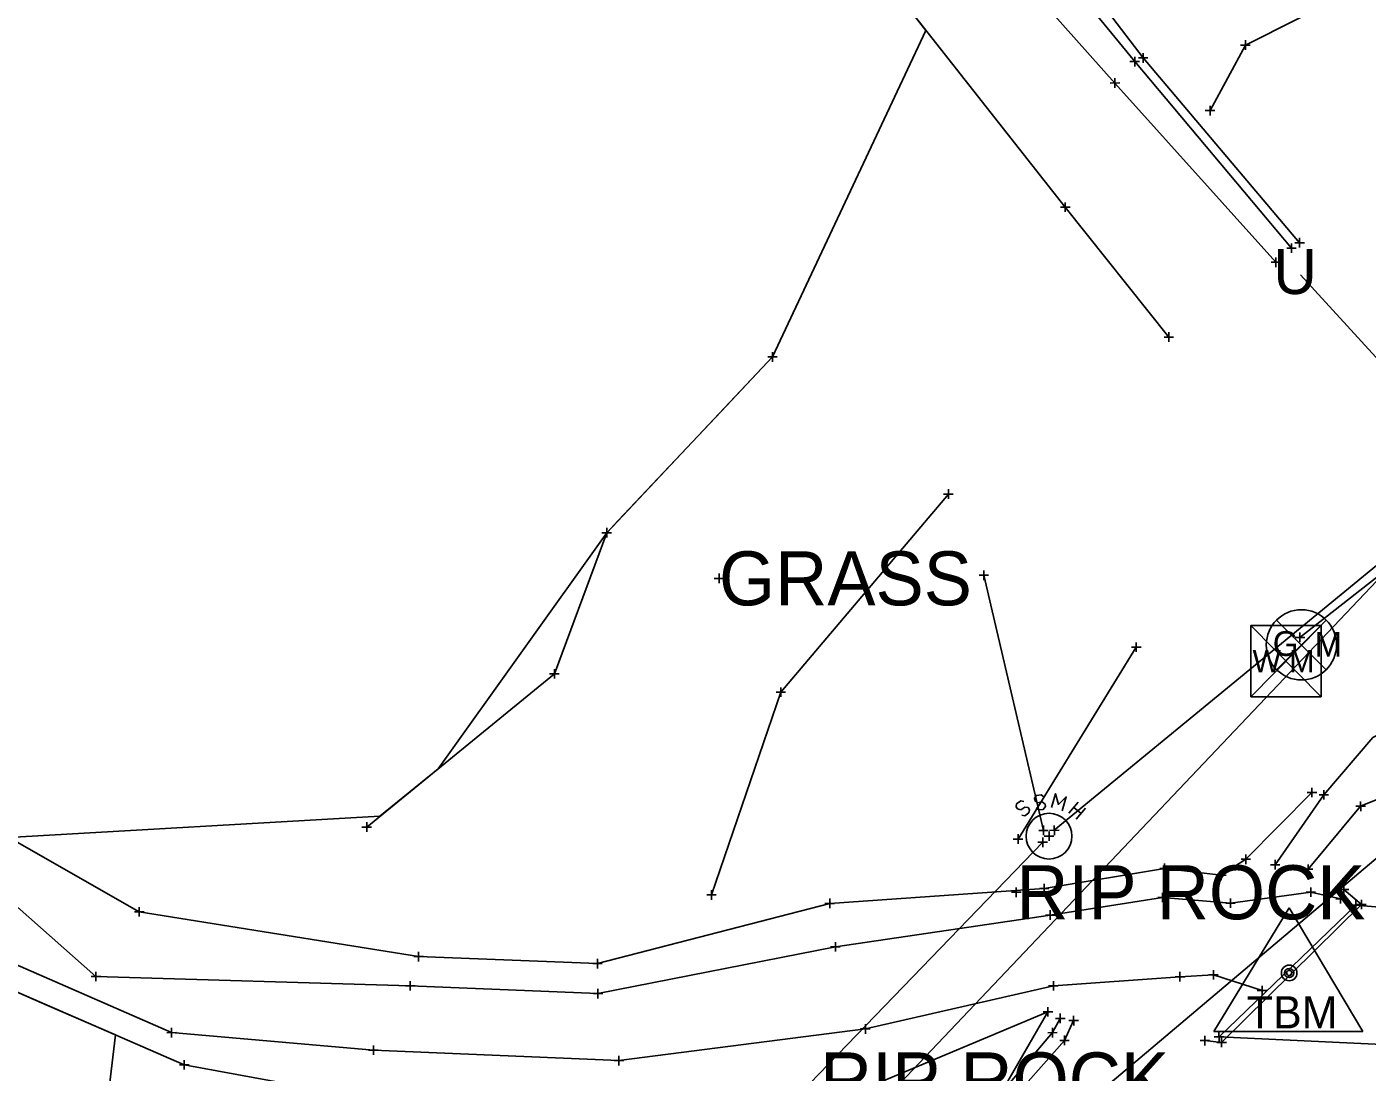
# Model space of a CAD drawing. Extents: x -1 to 1157254, y -1 to 2021979.
# Drawn here: x 1149359.7 to 1149538.4, y 2019032.4 to 2019171.7 of the extents above; entities that cross this region are included whole.
import ezdxf

# ---------------------------------------------------------------- set-up
doc = ezdxf.new("R2010")
doc.units = 0
for name, color, linetype in [('S_AREA_CALC', 7, 'Continuous'), ('S_BUILDING_ANNOT', 7, 'Continuous'), ('S_CAL_CORNER_ANNOT', 7, 'Continuous'), ('S_CONTOUR_ANNOT', 7, 'Continuous'), ('S_CONTOUR_MAJOR', 7, 'Continuous'), ('S_CONTOUR_MINOR', 7, 'Continuous'), ('S_CTL_TABLE', 7, 'Continuous'), ('S_DRIVEWAY_ANNOT', 7, 'Continuous'), ('S_DROP_INLET', 7, 'Continuous'), ('S_EDGE_BITUMINOUS_ANNOT', 7, 'Continuous'), ('S_ELECTRIC_UTILITIES_ANNOT', 7, 'Continuous'), ('S_ENV_CONSTRAINT', 7, 'Continuous'), ('S_EXIST_ROW', 7, 'Continuous'), ('S_GAS_PUMP_ISLAND_ANNOT', 7, 'Continuous'), ('S_GATE', 7, 'Continuous')]:
    doc.layers.add(name, color=color, linetype=linetype)

msp = doc.modelspace()

# ---------------------------------------------------------------- linework, layer by layer
at = {"layer": 'S_AREA_CALC'}
for p, q in [((1149527.99, 2019054.31), (1149517.96, 2019037.8)), ((1149527.99, 2019054.31), (1149537.81, 2019037.8)), ((1149517.96, 2019037.8), (1149537.81, 2019037.8))]:
    msp.add_line(p, q, dxfattribs=at)
for radius in [1.04, 0.609, 0.344]:
    msp.add_circle((1149527.99, 2019045.61), radius, dxfattribs=at)
at = {"layer": 'S_BUILDING_ANNOT'}
for p, q in [((1149507.41, 2019166.42), (1149507.41, 2019167.7)), ((1149508.54, 2019166.9), (1149508.54, 2019168.18)), ((1149506.77, 2019167.06), (1149508.05, 2019167.06)), ((1149507.41, 2019167.06), (1149507.41, 2019167.06)), ((1149507.9, 2019167.54), (1149509.17, 2019167.54)), ((1149508.54, 2019167.54), (1149508.54, 2019167.54)), ((1149504.13, 2019164.19), (1149505.41, 2019164.2)), ((1149504.77, 2019163.56), (1149504.77, 2019164.83)), ((1149504.77, 2019164.19), (1149504.77, 2019164.19)), ((1149498.15, 2019147.01), (1149498.15, 2019148.28)), ((1149497.51, 2019147.65), (1149498.78, 2019147.65)), ((1149498.15, 2019147.65), (1149498.15, 2019147.65)), ((1149528.31, 2019141.56), (1149528.31, 2019142.83)), ((1149528.74, 2019142.92), (1149530.01, 2019142.92)), ((1149529.37, 2019142.29), (1149529.37, 2019143.56)), ((1149529.37, 2019142.92), (1149529.37, 2019142.92)), ((1149526.22, 2019139.68), (1149526.22, 2019140.95)), ((1149527.67, 2019142.2), (1149528.94, 2019142.2)), ((1149528.31, 2019142.2), (1149528.31, 2019142.2)), ((1149525.59, 2019140.31), (1149526.86, 2019140.32)), ((1149526.22, 2019140.32), (1149526.22, 2019140.32)), ((1149511.31, 2019130.35), (1149512.59, 2019130.35)), ((1149511.95, 2019129.71), (1149511.95, 2019130.98)), ((1149511.95, 2019130.35), (1149511.95, 2019130.35)), ((1149451.36, 2019098.19), (1149452.63, 2019098.19)), ((1149451.99, 2019097.56), (1149451.99, 2019098.83)), ((1149451.99, 2019098.19), (1149451.99, 2019098.19)), ((1149486.66, 2019098.6), (1149487.93, 2019098.6)), ((1149487.29, 2019097.97), (1149487.29, 2019099.24)), ((1149487.29, 2019098.6), (1149487.29, 2019098.6)), ((1149529.43, 2019089.69), (1149529.42, 2019090.97)), ((1149528.79, 2019090.33), (1149530.06, 2019090.33)), ((1149529.43, 2019090.33), (1149529.43, 2019090.33)), ((1149531.98, 2019069.35), (1149533.25, 2019069.35)), ((1149532.62, 2019068.71), (1149532.62, 2019069.98)), ((1149532.62, 2019069.35), (1149532.62, 2019069.35)), ((1149536.88, 2019067.83), (1149538.15, 2019067.83)), ((1149537.52, 2019067.19), (1149537.51, 2019068.47)), ((1149537.51, 2019067.83), (1149537.51, 2019067.83)), ((1149494.6, 2019064.61), (1149495.87, 2019064.61)), ((1149494.6, 2019064.61), (1149495.87, 2019064.61)), ((1149495.23, 2019063.97), (1149495.23, 2019065.24)), ((1149495.23, 2019063.97), (1149495.23, 2019065.24)), ((1149495.23, 2019064.61), (1149495.23, 2019064.61)), ((1149495.23, 2019064.61), (1149495.23, 2019064.61)), ((1149495.98, 2019063.2), (1149495.98, 2019064.47)), ((1149496.05, 2019064.61), (1149497.32, 2019064.62)), ((1149496.05, 2019064.61), (1149497.32, 2019064.62)), ((1149496.69, 2019063.98), (1149496.68, 2019065.25)), ((1149496.69, 2019063.98), (1149496.68, 2019065.25)), ((1149496.68, 2019064.62), (1149496.68, 2019064.62)), ((1149496.68, 2019064.62), (1149496.68, 2019064.62)), ((1149494.5, 2019063.02), (1149495.78, 2019063.02)), ((1149494.5, 2019063.02), (1149495.78, 2019063.02)), ((1149495.14, 2019062.38), (1149495.14, 2019063.66)), ((1149495.14, 2019062.38), (1149495.14, 2019063.66)), ((1149495.14, 2019063.02), (1149495.14, 2019063.02)), ((1149495.14, 2019063.02), (1149495.14, 2019063.02)), ((1149495.34, 2019063.84), (1149496.62, 2019063.84)), ((1149495.98, 2019063.84), (1149495.98, 2019063.84)), ((1149526.12, 2019059.4), (1149526.12, 2019060.67)), ((1149525.49, 2019060.03), (1149526.76, 2019060.03)), ((1149526.12, 2019060.03), (1149526.12, 2019060.03)), ((1149529.88, 2019059.45), (1149531.15, 2019059.45)), ((1149530.52, 2019058.81), (1149530.52, 2019060.08)), ((1149530.52, 2019059.45), (1149530.52, 2019059.45)), ((1149491.61, 2019055.73), (1149491.61, 2019057)), ((1149530.88, 2019055.75), (1149530.87, 2019057.02)), ((1149535.28, 2019056.1), (1149535.28, 2019057.37)), ((1149490.97, 2019056.36), (1149492.25, 2019056.36)), ((1149491.61, 2019056.36), (1149491.61, 2019056.36)), ((1149510.48, 2019055.68), (1149511.76, 2019055.68)), ((1149511.12, 2019055.04), (1149511.12, 2019056.31)), ((1149511.12, 2019055.68), (1149511.12, 2019055.68)), ((1149520.17, 2019054.27), (1149520.17, 2019055.55)), ((1149530.24, 2019056.38), (1149531.51, 2019056.39)), ((1149530.87, 2019056.39), (1149530.87, 2019056.39)), ((1149534.19, 2019055.5), (1149535.47, 2019055.5)), ((1149534.65, 2019056.73), (1149535.92, 2019056.74)), ((1149534.83, 2019054.86), (1149534.83, 2019056.13)), ((1149534.83, 2019055.5), (1149534.83, 2019055.5)), ((1149535.28, 2019056.74), (1149535.28, 2019056.74)), ((1149536.88, 2019053.99), (1149536.88, 2019055.27)), ((1149537.63, 2019054.09), (1149537.62, 2019055.36)), ((1149495.51, 2019053.32), (1149496.78, 2019053.32)), ((1149496.15, 2019052.68), (1149496.15, 2019053.96)), ((1149496.15, 2019053.32), (1149496.15, 2019053.32)), ((1149519.53, 2019054.91), (1149520.8, 2019054.91)), ((1149520.17, 2019054.91), (1149520.17, 2019054.91)), ((1149536.24, 2019054.63), (1149537.52, 2019054.63)), ((1149536.88, 2019054.63), (1149536.88, 2019054.63)), ((1149536.99, 2019054.73), (1149538.26, 2019054.73)), ((1149537.63, 2019054.73), (1149537.63, 2019054.73)), ((1149467.51, 2019048.46), (1149467.5, 2019049.73)), ((1149466.87, 2019049.09), (1149468.14, 2019049.09)), ((1149467.51, 2019049.09), (1149467.51, 2019049.09)), ((1149368.29, 2019045.14), (1149369.57, 2019045.15)), ((1149368.93, 2019044.51), (1149368.93, 2019045.78)), ((1149368.93, 2019045.14), (1149368.93, 2019045.14)), ((1149410.83, 2019043.26), (1149410.83, 2019044.53)), ((1149496.56, 2019043.26), (1149496.56, 2019044.54)), ((1149512.8, 2019045.1), (1149514.07, 2019045.1)), ((1149513.43, 2019044.46), (1149513.43, 2019045.74)), ((1149513.43, 2019045.1), (1149513.43, 2019045.1)), ((1149517.26, 2019045.36), (1149518.53, 2019045.37)), ((1149517.9, 2019044.73), (1149517.9, 2019046)), ((1149517.9, 2019045.37), (1149517.9, 2019045.37)), ((1149410.2, 2019043.89), (1149411.47, 2019043.89)), ((1149410.83, 2019043.89), (1149410.83, 2019043.89)), ((1149435.22, 2019042.86), (1149436.49, 2019042.86)), ((1149435.85, 2019042.22), (1149435.85, 2019043.5)), ((1149435.85, 2019042.86), (1149435.85, 2019042.86)), ((1149495.92, 2019043.9), (1149497.2, 2019043.9)), ((1149496.56, 2019043.9), (1149496.56, 2019043.9)), ((1149523.74, 2019043.27), (1149525.01, 2019043.27)), ((1149524.37, 2019042.63), (1149524.37, 2019043.9)), ((1149524.37, 2019043.27), (1149524.37, 2019043.27)), ((1149496.85, 2019039.56), (1149498.12, 2019039.56)), ((1149497.48, 2019038.92), (1149497.48, 2019040.2)), ((1149497.48, 2019039.56), (1149497.48, 2019039.56)), ((1149498.63, 2019039.26), (1149499.9, 2019039.27)), ((1149499.27, 2019038.63), (1149499.26, 2019039.9)), ((1149499.26, 2019039.26), (1149499.26, 2019039.26)), ((1149378.38, 2019037.65), (1149379.66, 2019037.66)), ((1149379.02, 2019037.02), (1149379.02, 2019038.29)), ((1149379.02, 2019037.66), (1149379.02, 2019037.66)), ((1149470.87, 2019038.15), (1149472.14, 2019038.15)), ((1149471.51, 2019037.51), (1149471.51, 2019038.79)), ((1149471.51, 2019038.15), (1149471.51, 2019038.15)), ((1149495.8, 2019037.65), (1149497.07, 2019037.66)), ((1149496.44, 2019037.02), (1149496.43, 2019038.29)), ((1149496.43, 2019037.66), (1149496.43, 2019037.66)), ((1149498.05, 2019035.99), (1149498.04, 2019037.26)), ((1149516.74, 2019035.96), (1149516.74, 2019037.23)), ((1149518.64, 2019036.44), (1149518.63, 2019037.72)), ((1149405.93, 2019034.68), (1149405.93, 2019035.95)), ((1149497.41, 2019036.62), (1149498.68, 2019036.62)), ((1149498.04, 2019036.62), (1149498.04, 2019036.62)), ((1149516.11, 2019036.59), (1149517.38, 2019036.59)), ((1149516.74, 2019036.59), (1149516.74, 2019036.59)), ((1149518, 2019037.08), (1149519.27, 2019037.08)), ((1149518.35, 2019036.34), (1149519.63, 2019036.34)), ((1149518.64, 2019037.08), (1149518.64, 2019037.08)), ((1149518.99, 2019035.71), (1149518.99, 2019036.98)), ((1149518.99, 2019036.34), (1149518.99, 2019036.34)), ((1149405.29, 2019035.32), (1149406.57, 2019035.32)), ((1149405.93, 2019035.32), (1149405.93, 2019035.32)), ((1149438.01, 2019033.94), (1149439.29, 2019033.94)), ((1149438.65, 2019033.3), (1149438.65, 2019034.57)), ((1149438.65, 2019033.94), (1149438.65, 2019033.94))]:
    msp.add_line(p, q, dxfattribs=at)
at = {"layer": 'S_CAL_CORNER_ANNOT'}
for p, q in [((1149526.31, 2019086.02), (1149532.92, 2019092.64)), ((1149526.31, 2019092.64), (1149532.92, 2019086.02))]:
    msp.add_line(p, q, dxfattribs=at)
msp.add_lwpolyline([(1149620.7, 2019164.72), (1149555.24, 2019110.5), (1149529.43, 2019090.33)], dxfattribs=at)
msp.add_circle((1149529.62, 2019089.33), 4.68, dxfattribs=at)
at = {"layer": 'S_CONTOUR_ANNOT'}
for p, q in [((1149522.9, 2019091.89), (1149532.24, 2019091.89)), ((1149522.9, 2019091.89), (1149522.9, 2019082.4)), ((1149522.9, 2019091.89), (1149532.24, 2019082.4)), ((1149532.24, 2019091.89), (1149522.9, 2019082.4)), ((1149532.24, 2019091.89), (1149532.24, 2019082.4)), ((1149522.9, 2019082.4), (1149532.24, 2019082.4))]:
    msp.add_line(p, q, dxfattribs=at)
for points in [[(1149931.59, 2019393.98), (1149688.42, 2019230.92), (1149605.65, 2019167.39), (1149471.25, 2019025.78), (1149394.11, 2018934.21), (1149347.84, 2018899.68), (1149226.01, 2018779.47), (1149177.83, 2018729.86), (1148942.89, 2018495.75), (1148824.88, 2018414.4), (1148656.17, 2018321.62), (1148428.99, 2018204.95), (1148398.58, 2018185.48), (1148319.88, 2018123.12), (1148171.01, 2018007.64), (1148133.82, 2017978.13)], [(1149934.92, 2019374.11), (1149784.56, 2019258.12), (1149678.43, 2019178.13), (1149472.4, 2019004.16), (1149427, 2018951.04), (1149358.36, 2018900), (1149291.74, 2018823.41), (1149233.45, 2018767.69), (1149177.23, 2018710.91), (1149078.39, 2018616.37), (1148964.19, 2018499.8), (1148972, 2018491.15), (1148988.16, 2018467.17), (1149002.28, 2018452.45)]]:
    msp.add_lwpolyline(points, dxfattribs=at)
at = {"layer": 'S_CONTOUR_MINOR'}
for p, q in [((1149491.65, 2019068.14), (1149491.58, 2019067.75)), ((1149491.58, 2019067.75), (1149491.77, 2019067.48)), ((1149492.2, 2019068.53), (1149491.65, 2019068.14)), ((1149492.62, 2019068.45), (1149492.2, 2019068.53)), ((1149492.2, 2019067.36), (1149492.74, 2019067.71)), ((1149492.74, 2019067.71), (1149493.2, 2019067.64)), ((1149493.2, 2019067.64), (1149493.36, 2019067.36)), ((1149498.63, 2019066.9), (1149499.87, 2019068.37)), ((1149499.29, 2019067.67), (1149500.25, 2019066.86)), ((1149500.83, 2019067.56), (1149499.6, 2019066.09)), ((1149491.77, 2019067.48), (1149492.2, 2019067.36)), ((1149492.74, 2019066.55), (1149492.35, 2019066.63)), ((1149493.28, 2019066.94), (1149492.74, 2019066.55)), ((1149493.36, 2019067.36), (1149493.28, 2019066.94))]:
    msp.add_line(p, q, dxfattribs=at)
for points in [[(1149889.62, 2019387.25), (1149496.68, 2019064.62)], [(1149495.23, 2019064.61), (1149487.29, 2019098.6)], [(1149495.3, 2019069.07), (1149494.95, 2019069.34), (1149494.29, 2019069.26), (1149494.06, 2019068.91), (1149494.09, 2019068.6), (1149494.44, 2019068.29), (1149495.06, 2019068.41), (1149495.45, 2019068.1), (1149495.49, 2019067.79), (1149495.22, 2019067.4), (1149494.6, 2019067.33), (1149494.25, 2019067.6)], [(1149497.74, 2019067.21), (1149498.28, 2019069.07), (1149497.23, 2019068.06), (1149496.84, 2019069.49), (1149496.3, 2019067.64)], [(1149495.14, 2019063.02), (1149452.95, 2019019.35)]]:
    msp.add_lwpolyline(points, dxfattribs=at)
msp.add_circle((1149495.98, 2019063.84), 3.05, dxfattribs=at)
at = {"layer": 'S_CTL_TABLE'}
for p, q in [((1149522.15, 2019168.63), (1149522.15, 2019169.9)), ((1149521.52, 2019169.26), (1149522.79, 2019169.26)), ((1149522.15, 2019169.26), (1149522.15, 2019169.26)), ((1149516.8, 2019160.52), (1149518.07, 2019160.52)), ((1149517.44, 2019159.89), (1149517.44, 2019161.16)), ((1149517.44, 2019160.52), (1149517.44, 2019160.52)), ((1149459.12, 2019127.06), (1149459.12, 2019128.34)), ((1149458.49, 2019127.7), (1149459.76, 2019127.7)), ((1149459.12, 2019127.7), (1149459.12, 2019127.7)), ((1149481.93, 2019109.42), (1149483.2, 2019109.42)), ((1149482.56, 2019108.79), (1149482.56, 2019110.06)), ((1149482.56, 2019109.42), (1149482.56, 2019109.42)), ((1149436.39, 2019104.27), (1149437.67, 2019104.28)), ((1149437.03, 2019103.64), (1149437.03, 2019104.91)), ((1149437.03, 2019104.28), (1149437.03, 2019104.28)), ((1149506.98, 2019089.01), (1149508.25, 2019089.01)), ((1149507.61, 2019088.38), (1149507.61, 2019089.65)), ((1149507.61, 2019089.01), (1149507.61, 2019089.01)), ((1149429.4, 2019085.47), (1149430.67, 2019085.47)), ((1149430.04, 2019084.83), (1149430.04, 2019086.1)), ((1149430.04, 2019085.47), (1149430.04, 2019085.47)), ((1149460.23, 2019082.4), (1149460.22, 2019083.67)), ((1149459.59, 2019083.04), (1149460.86, 2019083.04)), ((1149460.22, 2019083.04), (1149460.22, 2019083.04)), ((1149530.39, 2019069.65), (1149531.66, 2019069.66)), ((1149531.03, 2019069.02), (1149531.02, 2019070.29)), ((1149531.03, 2019069.65), (1149531.03, 2019069.65)), ((1149404.4, 2019065.06), (1149405.68, 2019065.06)), ((1149405.04, 2019064.43), (1149405.04, 2019065.7)), ((1149405.04, 2019065.06), (1149405.04, 2019065.06)), ((1149491.86, 2019062.82), (1149491.86, 2019064.09)), ((1149491.22, 2019063.45), (1149492.49, 2019063.45)), ((1149491.86, 2019063.45), (1149491.86, 2019063.45)), ((1149521.57, 2019060.77), (1149522.84, 2019060.77)), ((1149522.21, 2019060.13), (1149522.21, 2019061.41)), ((1149522.21, 2019060.77), (1149522.21, 2019060.77)), ((1149510.73, 2019059.55), (1149512, 2019059.55)), ((1149511.37, 2019058.91), (1149511.36, 2019060.19)), ((1149511.36, 2019059.55), (1149511.36, 2019059.55)), ((1149518.29, 2019058.62), (1149519.57, 2019058.63)), ((1149518.93, 2019057.99), (1149518.93, 2019059.26)), ((1149518.93, 2019058.63), (1149518.93, 2019058.63)), ((1149494.7, 2019056.85), (1149495.97, 2019056.85)), ((1149495.33, 2019056.21), (1149495.33, 2019057.49)), ((1149495.33, 2019056.85), (1149495.33, 2019056.85)), ((1149450.36, 2019056), (1149451.63, 2019056.01)), ((1149450.99, 2019055.37), (1149450.99, 2019056.64)), ((1149450.99, 2019056.01), (1149450.99, 2019056.01)), ((1149466.74, 2019054.25), (1149466.74, 2019055.52)), ((1149374.08, 2019053.77), (1149375.35, 2019053.77)), ((1149374.71, 2019053.13), (1149374.71, 2019054.4)), ((1149374.71, 2019053.77), (1149374.71, 2019053.77)), ((1149466.1, 2019054.88), (1149467.37, 2019054.88)), ((1149466.74, 2019054.88), (1149466.74, 2019054.88)), ((1149411.94, 2019047.16), (1149411.94, 2019048.43)), ((1149411.3, 2019047.8), (1149412.58, 2019047.8)), ((1149411.94, 2019047.8), (1149411.94, 2019047.8)), ((1149435.15, 2019046.85), (1149436.43, 2019046.86)), ((1149435.79, 2019046.22), (1149435.79, 2019047.49)), ((1149435.79, 2019046.85), (1149435.79, 2019046.85)), ((1149495.83, 2019039.8), (1149495.83, 2019041.07)), ((1149495.2, 2019040.44), (1149496.47, 2019040.44)), ((1149495.83, 2019040.44), (1149495.83, 2019040.44)), ((1149380.72, 2019032.73), (1149380.72, 2019034)), ((1149380.08, 2019033.36), (1149381.35, 2019033.36)), ((1149380.72, 2019033.36), (1149380.72, 2019033.36))]:
    msp.add_line(p, q, dxfattribs=at)
at = {"layer": 'S_DRIVEWAY_ANNOT'}
for points in [[(1149449.39, 2019240), (1149468.94, 2019221.1), (1149484.25, 2019199.29), (1149508.54, 2019167.54), (1149529.37, 2019142.92)], [(1149449.24, 2019238.46), (1149466.52, 2019219.95), (1149485.53, 2019193.75), (1149507.41, 2019167.06), (1149528.31, 2019142.2)], [(1149534.83, 2019055.5), (1149530.87, 2019056.39), (1149520.17, 2019054.91), (1149511.12, 2019055.68), (1149496.15, 2019053.32), (1149467.51, 2019049.09), (1149435.85, 2019042.86), (1149410.83, 2019043.89), (1149368.93, 2019045.14), (1149349.86, 2019061.99), (1149327.53, 2019081.98), (1149311.1, 2019084.98), (1149301.91, 2019105.65), (1149289.87, 2019144.23)], [(1149524.37, 2019043.27), (1149517.9, 2019045.37), (1149513.43, 2019045.1), (1149496.56, 2019043.9), (1149471.51, 2019038.15), (1149438.65, 2019033.94), (1149405.93, 2019035.32), (1149379.02, 2019037.66), (1149344.01, 2019052.96), (1149330.51, 2019065.25), (1149302.98, 2019080.53), (1149290.57, 2019096.53), (1149286.19, 2019112.23), (1149267.34, 2019122.7)], [(1149546.47, 2019080.52), (1149539.15, 2019076.99), (1149532.62, 2019069.35), (1149526.12, 2019060.03)], [(1149549.74, 2019079.27), (1149544.77, 2019070.76), (1149537.51, 2019067.83), (1149530.52, 2019059.45)], [(1149497.48, 2019039.56), (1149496.43, 2019037.66), (1149489.07, 2019028.95), (1149475.74, 2019009.67), (1149458.51, 2018991.72), (1149431.27, 2018961.65), (1149410.16, 2018936.96), (1149396.78, 2018927.66), (1149395.88, 2018925.02)], [(1149499.26, 2019039.26), (1149498.04, 2019036.62), (1149490.07, 2019027.66), (1149477.96, 2019008.76), (1149461.47, 2018989.26), (1149432.96, 2018958.61), (1149408.48, 2018939.72), (1149397.88, 2018925.65), (1149396.76, 2018924.74)]]:
    msp.add_lwpolyline(points, dxfattribs=at)
at = {"layer": 'S_DROP_INLET'}
msp.add_lwpolyline([(1149584.08, 2019135.06), (1149577.18, 2019112.53), (1149568.36, 2019111.66), (1149550.08, 2019116.17), (1149529.52, 2019138.63)], dxfattribs=at)
at = {"layer": 'S_EDGE_BITUMINOUS_ANNOT'}
for points in [[(1149615.7, 2019215.56), (1149586.32, 2019202), (1149570.47, 2019193.58), (1149522.15, 2019169.26), (1149517.44, 2019160.52)], [(1149531.03, 2019069.65), (1149522.21, 2019060.77), (1149518.93, 2019058.63), (1149511.36, 2019059.55), (1149495.33, 2019056.85), (1149466.74, 2019054.88), (1149435.79, 2019046.85), (1149411.94, 2019047.8), (1149374.71, 2019053.77), (1149355.27, 2019064.82), (1149332.05, 2019084.08), (1149313.06, 2019089.71), (1149307.34, 2019106.38), (1149293.06, 2019144.66)], [(1149459.12, 2019127.7), (1149437.03, 2019104.28), (1149430.04, 2019085.47), (1149405.04, 2019065.06)], [(1149470.95, 2019015.88), (1149480.9, 2019023.42), (1149490.47, 2019031.18), (1149495.83, 2019040.44), (1149472.33, 2019030.55), (1149438.25, 2019027.17), (1149405.64, 2019028.8), (1149380.72, 2019033.36), (1149343.09, 2019049.73), (1149326.07, 2019062), (1149301.59, 2019079.71), (1149283.88, 2019097.02), (1149282.36, 2019113.17), (1149265.52, 2019117.42)], [(1149482.56, 2019109.42), (1149460.22, 2019083.04), (1149450.99, 2019056.01)], [(1149507.61, 2019089.01), (1149491.86, 2019063.45)]]:
    msp.add_lwpolyline(points, dxfattribs=at)
at = {"layer": 'S_ELECTRIC_UTILITIES_ANNOT'}
msp.add_lwpolyline([(1149535.28, 2019056.74), (1149537.63, 2019054.73), (1149518.99, 2019036.34), (1149516.74, 2019036.59)], dxfattribs=at)
at = {"layer": 'S_ENV_CONSTRAINT'}
for points in [[(1149443.36, 2019233.91), (1149461.12, 2019214.82), (1149481.03, 2019190.82), (1149504.77, 2019164.19), (1149526.22, 2019140.32)], [(1149511.95, 2019130.35), (1149498.15, 2019147.65), (1149477.06, 2019174.4), (1149456.18, 2019198.82), (1149432.74, 2019223.43)]]:
    msp.add_lwpolyline(points, dxfattribs=at)
at = {"layer": 'S_EXIST_ROW'}
msp.add_lwpolyline([(1149589.51, 2019050.16), (1149536.88, 2019054.63), (1149518.64, 2019037.08), (1149572.53, 2019034.57)], close=True, dxfattribs=at)
at = {"layer": 'S_GAS_PUMP_ISLAND_ANNOT'}
for points in [[(1149477.06, 2019174.4), (1149479.58, 2019171.2), (1149459.12, 2019127.7), (1149452.26, 2019120.43), (1149445.4, 2019113.15), (1149438.54, 2019105.88), (1149437.03, 2019104.28), (1149414.54, 2019072.82), (1149406.8, 2019066.5), (1149357.35, 2019063.64)], [(1149353.22, 2019045.32), (1149362.38, 2019041.34), (1149371.55, 2019037.35), (1149365.9, 2018990.03), (1149371.62, 2018981.83), (1149380.22, 2018944.38), (1149353.45, 2018903.35)]]:
    msp.add_lwpolyline(points, dxfattribs=at)

# ---------------------------------------------------------------- texts
at = {"layer": 'S_AREA_CALC'}
msp.add_text('TBM', height=4.285, dxfattribs=at).set_placement((1149522.34, 2019038.23))
at = {"layer": 'S_CAL_CORNER_ANNOT'}
for s, p in [('G', (1149525.8, 2019087.86)), ('M', (1149531.36, 2019087.76))]:
    msp.add_text(s, height=3.3, dxfattribs=at).set_placement(p)
at = {"layer": 'S_CONTOUR_ANNOT'}
msp.add_text('W M', height=2.999, dxfattribs=at).set_placement((1149523.11, 2019085.66))
at = {"layer": 'S_CONTOUR_MAJOR'}
msp.add_text('U', height=6, dxfattribs=at).set_placement((1149525.89, 2019136.08))
at = {"layer": 'S_GATE'}
for s, p in [('GRASS', (1149451.99, 2019094.59)), ('RIP ROCK', (1149491.61, 2019052.76)), ('RIP ROCK', (1149465.44, 2019027.82))]:
    msp.add_text(s, height=7.2, dxfattribs=at).set_placement(p)

doc.saveas('drawing.dxf')
